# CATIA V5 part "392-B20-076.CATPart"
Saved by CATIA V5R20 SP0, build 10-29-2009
Part number: 392-B20-076
Definition: NONE
Nomenclature: 392-B20-076
Source: Unknown
Description: 392-B20-076
Bounding box of the stored display mesh (mm): x 0 to 76, y -9.276 to 9.276, z -9.2 to 9.2
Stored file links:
  C:\Users\Utente\Desktop\IO LAVORO\3D X SITO CF\X SITO\3D files 392B\392-B20-076.CATPart
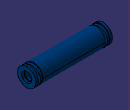
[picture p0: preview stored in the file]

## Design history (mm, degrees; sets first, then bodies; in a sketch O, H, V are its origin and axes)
Body1 "392-B20-076" (main body)
  Solid1: solid without history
